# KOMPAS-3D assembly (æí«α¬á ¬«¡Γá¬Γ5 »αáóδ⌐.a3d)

Referenced files in D:\МОДЕЛЬ ТАНКА Т90\ДЕТАЛИ\БАШНЯ\башня сварная\НАВЕСКА\: контакт5.m3d
Referenced files in D:\МОДЕЛЬ ТАНКА Т90\ДЕТАЛИ\БАШНЯ\башня сварная\: контакт5-1.m3d
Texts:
  Сборка контакт5
  stalker61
